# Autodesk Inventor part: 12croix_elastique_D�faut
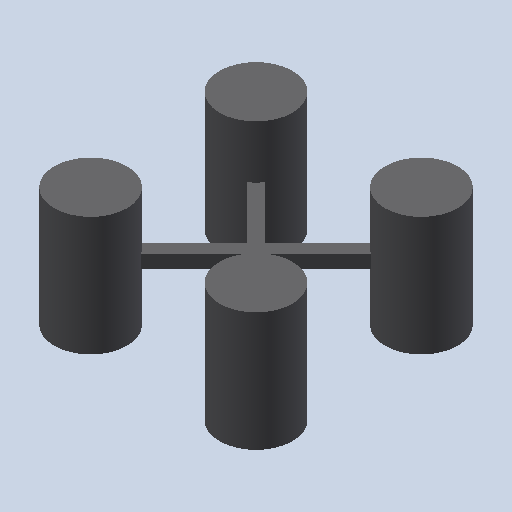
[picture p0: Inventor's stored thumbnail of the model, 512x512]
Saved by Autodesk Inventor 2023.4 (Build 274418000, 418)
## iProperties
Created: 2011-01
Part Number: 12croix_elastique_D�faut
Document SubType Name: Modeling
Designer: eric
Density: 1 g/cm^3
Mass: 0.878715 g
Surface Area: 8.99989 cm^2
Volume: 0.878715 cm^3
Material: Générique
Appearance: Yellow
Author: eric
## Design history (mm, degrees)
feature "Base1"
node "Corps solides"
node "Corps surfaciques"
node "Solide1"
